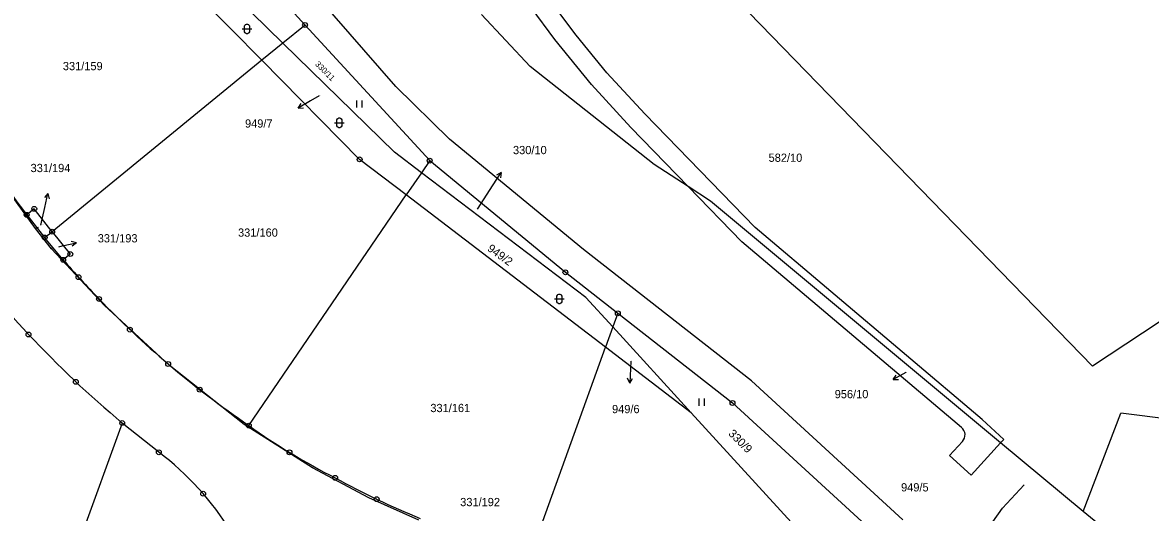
# Model space of a CAD drawing. Extents: x -770973 to -770265, y -1049936 to -1049427.
# Drawn here: x -770637.6 to -770521.2, y -1049647.3 to -1049596.8 of the extents above; entities that cross this region are included whole.
import ezdxf

# ---------------------------------------------------------------- set-up
doc = ezdxf.new("R2010")
doc.units = 0
for name, color, linetype in [('Vrstva 1', 7, 'Continuous'), ('Vrstva 13', 7, 'Continuous'), ('Vrstva 14', 7, 'Continuous'), ('Vrstva 16', 7, 'Continuous'), ('Vrstva 23', 7, 'Continuous'), ('Vrstva 28', 7, 'Continuous'), ('Vrstva 50', 7, 'Continuous')]:
    doc.layers.add(name, color=color, linetype=linetype)

msp = doc.modelspace()

# ---------------------------------------------------------------- linework, layer by layer
at = {"layer": 'Vrstva 1'}
for p, q in [((-770610.71, -1049598.92), (-770619.91, -1049589.93)), ((-770599.06, -1049603.4), (-770609.02, -1049591.96)), ((-770612.88, -1049600.68), (-770621.07, -1049592.38)), ((-770611.51, -1049593.68), (-770608.42, -1049597.05)), ((-770580.45, -1049598.11), (-770583.43, -1049594.09)), ((-770582.65, -1049598.54), (-770585.07, -1049595.25)), ((-770527.14, -1049632.24), (-770562.62, -1049595.76)), ((-770585.18, -1049601.33), (-770590.2, -1049595.98)), ((-770608.42, -1049597.05), (-770610.71, -1049598.92)), ((-770608.42, -1049597.05), (-770595.56, -1049611.04)), ((-770610.71, -1049598.92), (-770612.88, -1049600.68)), ((-770599.2, -1049610.17), (-770610.71, -1049598.92)), ((-770578.87, -1049603.2), (-770582.65, -1049598.54)), ((-770577.27, -1049601.97), (-770580.45, -1049598.11)), ((-770612.88, -1049600.68), (-770634.52, -1049618.37)), ((-770602.79, -1049610.91), (-770612.88, -1049600.68)), ((-770572.39, -1049611.42), (-770585.18, -1049601.33)), ((-770573.37, -1049606.22), (-770577.27, -1049601.97)), ((-770593.52, -1049608.83), (-770599.06, -1049603.4)), ((-770574.81, -1049607.61), (-770578.87, -1049603.2)), ((-770561.97, -1049617.94), (-770573.37, -1049606.22)), ((-770568.87, -1049613.72), (-770574.81, -1049607.61)), ((-770579.67, -1049620.21), (-770593.52, -1049608.83)), ((-770596.41, -1049612.28), (-770599.2, -1049610.17)), ((-770597.98, -1049614.58), (-770602.79, -1049610.91)), ((-770595.56, -1049611.04), (-770596.41, -1049612.28)), ((-770595.56, -1049611.04), (-770581.55, -1049622.55)), ((-770568.87, -1049613.72), (-770572.39, -1049611.42)), ((-770596.41, -1049612.28), (-770597.98, -1049614.58)), ((-770579.43, -1049625.15), (-770596.41, -1049612.28)), ((-770568.87, -1049613.72), (-770563.34, -1049619.41)), ((-770566.57, -1049615.23), (-770568.87, -1049613.72)), ((-770614.23, -1049638.36), (-770597.98, -1049614.58)), ((-770577.41, -1049630.29), (-770597.98, -1049614.58)), ((-770536.64, -1049640.14), (-770566.57, -1049615.23)), ((-770636.37, -1049616.01), (-770637.15, -1049616.63)), ((-770637.15, -1049616.63), (-770635.3, -1049618.97)), ((-770634.52, -1049618.37), (-770636.37, -1049616.01)), ((-770635.3, -1049618.97), (-770634.52, -1049618.37)), ((-770633.38, -1049621.27), (-770635.3, -1049618.97)), ((-770634.52, -1049618.37), (-770632.65, -1049620.67)), ((-770538.55, -1049637.73), (-770561.97, -1049617.94)), ((-770562.36, -1049633.74), (-770579.67, -1049620.21)), ((-770540.67, -1049638.56), (-770563.34, -1049619.41)), ((-770632.65, -1049620.67), (-770633.38, -1049621.27)), ((-770512.22, -1049622.34), (-770527.14, -1049632.24)), ((-770581.55, -1049622.55), (-770576.14, -1049626.78)), ((-770576.65, -1049628.19), (-770579.43, -1049625.15)), ((-770576.14, -1049626.78), (-770576.65, -1049628.19)), ((-770576.14, -1049626.78), (-770564.3, -1049636.03)), ((-770576.65, -1049628.19), (-770577.41, -1049630.29)), ((-770568.56, -1049637.05), (-770576.65, -1049628.19)), ((-770584.98, -1049651.2), (-770577.41, -1049630.29)), ((-770568.56, -1049637.05), (-770577.41, -1049630.29)), ((-770546.73, -1049648.09), (-770562.36, -1049633.74)), ((-770564.3, -1049636.03), (-770550.56, -1049648.64)), ((-770555.35, -1049651.47), (-770568.56, -1049637.05)), ((-770528.12, -1049647.23), (-770524.21, -1049637.09)), ((-770519.02, -1049637.74), (-770524.21, -1049637.09)), ((-770627.29, -1049638.1), (-770633.21, -1049654.38)), ((-770623.52, -1049641.11), (-770627.29, -1049638.1)), ((-770536.31, -1049639.78), (-770538.55, -1049637.73)), ((-770541.9, -1049641.45), (-770540.57, -1049640)), ((-770536.64, -1049640.14), (-770536.31, -1049639.78)), ((-770536.64, -1049640.14), (-770539.68, -1049643.47)), ((-770528.12, -1049647.23), (-770536.64, -1049640.14)), ((-770539.68, -1049643.47), (-770541.9, -1049641.45)), ((-770525.45, -1049649.4), (-770528.12, -1049647.23))]:
    msp.add_line(p, q, dxfattribs=at)
for centre, radius, start, end in [((-770565.39, -1049561.24), 90.64, 213.1334, 217.6631), ((-770557.12, -1049554.45), 109.2, 216.4607, 223.0213), ((-770557.89, -1049555.85), 99.89, 220.9109, 224.0455), ((-770557.08, -1049555.19), 100.93, 223.9961, 229.5605), ((-770556.91, -1049553.96), 109.69, 223.1369, 230.0911), ((-770556.4, -1049553.96), 102.31, 229.7165, 235.5802), ((-770572.47, -1049579.39), 72.26, 234.6964, 242.9609), ((-770541.3, -1049639.33), 0.994, 317.3974, 50.5476), ((-770641.67, -1049665.12), 30.1, 31.7359, 52.916), ((-770563.21, -1049566.92), 87.61, 241.2736, 247.648)]:
    msp.add_arc(centre, radius, start, end, dxfattribs=at)
at = {"layer": 'Vrstva 13'}
for p, q in [((-770606.97, -1049604.35), (-770607.85, -1049604.87)), ((-770590.61, -1049616.04), (-770588.99, -1049613.53)), ((-770635.69, -1049617.69), (-770635.29, -1049615.88)), ((-770633.82, -1049619.91), (-770633.48, -1049619.83)), ((-770574.81, -1049631.7), (-770574.84, -1049632.48))]:
    msp.add_line(p, q, dxfattribs=at)
at = {"layer": 'Vrstva 16'}
for p, q in [((-770607.85, -1049604.87), (-770609.14, -1049605.63)), ((-770609.14, -1049605.63), (-770608.84, -1049605.16)), ((-770609.14, -1049605.63), (-770608.58, -1049605.59)), ((-770588.99, -1049613.53), (-770588.18, -1049612.27)), ((-770588.18, -1049612.27), (-770588.66, -1049612.55)), ((-770588.18, -1049612.27), (-770588.24, -1049612.82)), ((-770634.96, -1049614.42), (-770635.32, -1049614.85)), ((-770635.29, -1049615.88), (-770634.96, -1049614.42)), ((-770634.96, -1049614.42), (-770634.83, -1049614.96)), ((-770633.48, -1049619.83), (-770632.01, -1049619.52)), ((-770632.01, -1049619.52), (-770632.55, -1049619.38)), ((-770632.01, -1049619.52), (-770632.45, -1049619.86)), ((-770574.84, -1049632.48), (-770574.9, -1049633.98)), ((-770546.42, -1049632.9), (-770547.74, -1049633.62)), ((-770574.9, -1049633.98), (-770575.13, -1049633.47)), ((-770574.9, -1049633.98), (-770574.63, -1049633.49)), ((-770547.74, -1049633.62), (-770547.42, -1049633.16)), ((-770547.74, -1049633.62), (-770547.18, -1049633.6))]:
    msp.add_line(p, q, dxfattribs=at)
at = {"layer": 'Vrstva 23'}
for p, q in [((-770614.91, -1049597.45), (-770613.91, -1049597.45)), ((-770614.66, -1049597.15), (-770614.61, -1049597.05)), ((-770614.66, -1049597.75), (-770614.66, -1049597.15)), ((-770614.61, -1049597.85), (-770614.66, -1049597.75)), ((-770614.61, -1049597.05), (-770614.56, -1049597)), ((-770614.56, -1049597.9), (-770614.61, -1049597.85)), ((-770614.56, -1049597), (-770614.46, -1049596.95)), ((-770614.46, -1049597.95), (-770614.56, -1049597.9)), ((-770614.46, -1049596.95), (-770614.36, -1049596.95)), ((-770614.36, -1049597.95), (-770614.46, -1049597.95)), ((-770614.36, -1049596.95), (-770614.26, -1049597)), ((-770614.26, -1049597.9), (-770614.36, -1049597.95)), ((-770614.26, -1049597), (-770614.21, -1049597.05)), ((-770614.21, -1049597.85), (-770614.26, -1049597.9)), ((-770614.21, -1049597.05), (-770614.16, -1049597.15)), ((-770614.16, -1049597.75), (-770614.21, -1049597.85)), ((-770614.16, -1049597.15), (-770614.16, -1049597.75)), ((-770603.07, -1049605.57), (-770603.07, -1049604.82)), ((-770602.57, -1049604.82), (-770602.57, -1049605.57)), ((-770605.39, -1049607.14), (-770604.39, -1049607.14)), ((-770605.14, -1049606.84), (-770605.09, -1049606.74)), ((-770605.14, -1049607.44), (-770605.14, -1049606.84)), ((-770605.09, -1049606.74), (-770605.04, -1049606.69)), ((-770605.04, -1049606.69), (-770604.94, -1049606.64)), ((-770604.94, -1049606.64), (-770604.84, -1049606.64)), ((-770604.84, -1049606.64), (-770604.74, -1049606.69)), ((-770604.74, -1049606.69), (-770604.69, -1049606.74)), ((-770604.69, -1049606.74), (-770604.64, -1049606.84)), ((-770604.64, -1049606.84), (-770604.64, -1049607.44)), ((-770605.09, -1049607.54), (-770605.14, -1049607.44)), ((-770605.04, -1049607.59), (-770605.09, -1049607.54)), ((-770604.94, -1049607.64), (-770605.04, -1049607.59)), ((-770604.84, -1049607.64), (-770604.94, -1049607.64)), ((-770604.74, -1049607.59), (-770604.84, -1049607.64)), ((-770604.69, -1049607.54), (-770604.74, -1049607.59)), ((-770604.64, -1049607.44), (-770604.69, -1049607.54)), ((-770582.38, -1049624.9), (-770582.33, -1049624.85)), ((-770582.33, -1049624.85), (-770582.23, -1049624.8)), ((-770582.23, -1049624.8), (-770582.13, -1049624.8)), ((-770582.13, -1049624.8), (-770582.03, -1049624.85)), ((-770582.03, -1049624.85), (-770581.98, -1049624.9)), ((-770582.68, -1049625.3), (-770581.68, -1049625.3)), ((-770582.43, -1049625), (-770582.38, -1049624.9)), ((-770582.43, -1049625.6), (-770582.43, -1049625)), ((-770582.38, -1049625.7), (-770582.43, -1049625.6)), ((-770582.33, -1049625.75), (-770582.38, -1049625.7)), ((-770582.23, -1049625.8), (-770582.33, -1049625.75)), ((-770582.13, -1049625.8), (-770582.23, -1049625.8)), ((-770582.03, -1049625.75), (-770582.13, -1049625.8)), ((-770581.98, -1049625.7), (-770582.03, -1049625.75)), ((-770581.98, -1049624.9), (-770581.93, -1049625)), ((-770581.93, -1049625.6), (-770581.98, -1049625.7)), ((-770581.93, -1049625), (-770581.93, -1049625.6)), ((-770567.74, -1049636.33), (-770567.74, -1049635.58)), ((-770567.24, -1049635.58), (-770567.24, -1049636.33))]:
    msp.add_line(p, q, dxfattribs=at)
at = {"layer": 'Vrstva 28'}
for centre, radius in [((-770608.42, -1049597.05), 0.25), ((-770608.42, -1049597.05), 0.005), ((-770602.79, -1049610.91), 0.25), ((-770595.56, -1049611.04), 0.25), ((-770602.79, -1049610.91), 0.005), ((-770595.56, -1049611.04), 0.005), ((-770637.15, -1049616.63), 0.25), ((-770637.15, -1049616.63), 0.005), ((-770636.37, -1049616.01), 0.25), ((-770636.37, -1049616.01), 0.005), ((-770635.3, -1049618.97), 0.25), ((-770635.3, -1049618.97), 0.005), ((-770634.52, -1049618.37), 0.25), ((-770634.52, -1049618.37), 0.005), ((-770633.38, -1049621.27), 0.25), ((-770633.38, -1049621.27), 0.005), ((-770632.65, -1049620.67), 0.25), ((-770632.65, -1049620.67), 0.005), ((-770581.55, -1049622.55), 0.25), ((-770631.8, -1049623.05), 0.25), ((-770631.8, -1049623.05), 0.005), ((-770581.55, -1049622.55), 0.005), ((-770629.69, -1049625.3), 0.25), ((-770629.69, -1049625.3), 0.005), ((-770576.14, -1049626.78), 0.25), ((-770576.14, -1049626.78), 0.005), ((-770626.5, -1049628.46), 0.25), ((-770636.96, -1049628.96), 0.25), ((-770636.96, -1049628.96), 0.005), ((-770626.5, -1049628.46), 0.005), ((-770622.55, -1049632.01), 0.25), ((-770622.55, -1049632.01), 0.005), ((-770632.08, -1049633.85), 0.25), ((-770632.08, -1049633.85), 0.005), ((-770619.29, -1049634.66), 0.25), ((-770619.29, -1049634.66), 0.005), ((-770564.3, -1049636.03), 0.25), ((-770564.3, -1049636.03), 0.005), ((-770627.29, -1049638.1), 0.25), ((-770627.29, -1049638.1), 0.005), ((-770614.23, -1049638.36), 0.25), ((-770614.23, -1049638.36), 0.005), ((-770623.52, -1049641.11), 0.25), ((-770623.52, -1049641.11), 0.005), ((-770610.03, -1049641.12), 0.25), ((-770610.03, -1049641.12), 0.005), ((-770605.32, -1049643.75), 0.25), ((-770605.32, -1049643.75), 0.005), ((-770618.94, -1049645.39), 0.25), ((-770618.94, -1049645.39), 0.005), ((-770601.03, -1049645.95), 0.25), ((-770601.03, -1049645.95), 0.005)]:
    msp.add_circle(centre, radius, dxfattribs=at)
at = {"layer": 'Vrstva 50'}
for p, q in [((-770636.24, -1049618.02), (-770639.54, -1049613.48)), ((-770636.24, -1049618.02), (-770635.92, -1049617.9)), ((-770634.59, -1049620.12), (-770636.24, -1049618.02)), ((-770634.59, -1049620.12), (-770634.44, -1049619.99)), ((-770629.11, -1049625.97), (-770634.59, -1049620.12)), ((-770622.46, -1049632.12), (-770629.11, -1049625.97)), ((-770614.69, -1049638.26), (-770622.46, -1049632.12)), ((-770607.66, -1049642.73), (-770614.69, -1049638.26)), ((-770601.84, -1049645.81), (-770607.66, -1049642.73)), ((-770536.43, -1049646.88), (-770534.19, -1049644.47)), ((-770596.69, -1049648.13), (-770601.84, -1049645.81)), ((-770541.42, -1049653.87), (-770536.43, -1049646.88))]:
    msp.add_line(p, q, dxfattribs=at)

# ---------------------------------------------------------------- texts
at = {"layer": 'Vrstva 14'}
for s, height, p in [('331/159', 0.85, (-770633.42, -1049601.71)), ('949/7', 0.05, (-770606.97, -1049604.35)), ('582/10', 0.85, (-770560.58, -1049611.16)), ('330/10', 0.05, (-770590.61, -1049616.04)), ('331/194', 0.05, (-770635.69, -1049617.69)), ('331/160', 0.85, (-770615.34, -1049618.88)), ('331/193', 0.05, (-770633.82, -1049619.91)), ('949/6', 0.05, (-770574.81, -1049631.7)), ('956/10', 0.05, (-770546.42, -1049632.9)), ('331/161', 0.85, (-770595.49, -1049636.97))]:
    msp.add_text(s, height=height, dxfattribs=at).set_placement(p)
for s, height, rotation, p in [('330/11', 0.6, 315, (-770607.43, -1049601.14)), ('949/2', 0.85, 324, (-770589.68, -1049620.26)), ('330/9', 0.85, 315, (-770564.79, -1049639.26))]:
    msp.add_text(s, height=height, rotation=rotation, dxfattribs=at).set_placement(p)
at = {"layer": 'Vrstva 16'}
for s, p in [('949/7', (-770614.62, -1049607.63)), ('330/10', (-770586.96, -1049610.37)), ('331/194', (-770636.75, -1049612.22)), ('331/193', (-770629.82, -1049619.47)), ('956/10', (-770553.76, -1049635.54)), ('949/6', (-770576.74, -1049637.08)), ('949/5', (-770546.91, -1049645.15)), ('331/192', (-770592.41, -1049646.67))]:
    msp.add_text(s, height=0.85, dxfattribs=at).set_placement(p)

doc.saveas('drawing.dxf')
